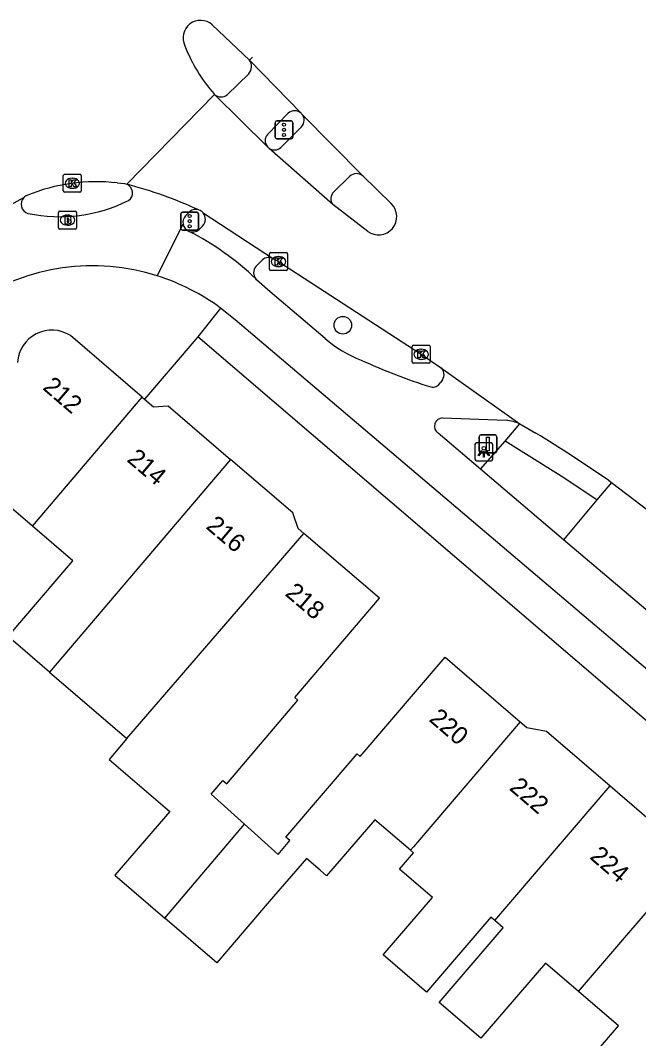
# Model space of a CAD drawing. Extents: x 162347 to 162868, y 381221 to 381813.
# Drawn here: x 162519 to 162553.4, y 381756.2 to 381812.9 of the extents above; entities that cross this region are included whole.
import ezdxf

# ---------------------------------------------------------------- set-up
doc = ezdxf.new("R2010")
doc.units = 0
for name, color, linetype in [('IMGEO_Berm_open', 7, 'Continuous'), ('IMGEO_Boom', 7, 'Continuous'), ('IMGEO_Brandkraan', 7, 'Continuous'), ('IMGEO_Fietspad_gesloten', 7, 'Continuous'), ('IMGEO_Kolk', 7, 'Continuous'), ('IMGEO_Lichtpunt', 7, 'Continuous'), ('IMGEO_Pand', 7, 'Continuous'), ('IMGEO_Pand_nummerreeks', 7, 'Continuous'), ('IMGEO_Rijbaan_lokaal_gesloten', 7, 'Continuous'), ('IMGEO_Rijbaan_regionaal_gesloten', 7, 'Continuous'), ('IMGEO_Verkeersbordpaal', 7, 'Continuous'), ('IMGEO_Verkeerseiland_groen', 7, 'Continuous'), ('IMGEO_Verkeersregelinstallatiepaal', 7, 'Continuous'), ('IMGEO_Voetpad_open', 7, 'Continuous')]:
    doc.layers.add(name, color=color, linetype=linetype)

msp = doc.modelspace()

# ---------------------------------------------------------------- linework, layer by layer
at = {"layer": 'IMGEO_Berm_open'}
msp.add_lwpolyline([(162551.096, 381786.201), (162549.242, 381783.987)], dxfattribs=at)
at = {"layer": 'IMGEO_Boom'}
msp.add_circle((162536.958, 381795.925), 0.489, dxfattribs=at)
at = {"layer": 'IMGEO_Brandkraan'}
for p, q in [((162521.217, 381802.273), (162522.069, 381802.273)), ((162521.142, 381801.347), (162521.142, 381802.199)), ((162521.63, 381802.053), (162521.655, 381802.053)), ((162522.143, 381802.199), (162522.143, 381801.347)), ((162522.069, 381801.273), (162521.217, 381801.273)), ((162521.653, 381801.493), (162521.628, 381801.493))]:
    msp.add_line(p, q, dxfattribs=at)
for points in [[(162521.217, 381802.273), (162522.069, 381802.273)], [(162521.142, 381801.347), (162521.142, 381802.199)], [(162521.49, 381801.973), (162521.49, 381801.573), (162521.703, 381801.573)], [(162521.721, 381801.973), (162521.49, 381801.973)], [(162521.669, 381801.892), (162521.615, 381801.892), (162521.615, 381801.816)], [(162521.615, 381801.816), (162521.668, 381801.816)], [(162521.677, 381801.74), (162521.615, 381801.74), (162521.615, 381801.659)], [(162521.615, 381801.659), (162521.677, 381801.659)], [(162522.143, 381802.199), (162522.143, 381801.347)], [(162522.069, 381801.273), (162521.217, 381801.273)]]:
    msp.add_lwpolyline(points, dxfattribs=at)
for centre, radius, start, end in [((162521.219, 381802.197), 0.0765, 91.552, 178.448), ((162521.219, 381802.197), 0.0765, 91.552, 178.448), ((162522.067, 381802.197), 0.0765, 1.552, 88.448), ((162522.067, 381802.197), 0.0765, 1.552, 88.448), ((162521.67, 381801.854), 0.0379, 267.8285, 90.9355), ((162521.678, 381801.699), 0.0404, 269.8759, 90.5077), ((162521.725, 381801.828), 0.145, 59.4692, 91.5367), ((162521.75, 381801.875), 0.0922, 285.5137, 58.1501), ((162521.755, 381801.683), 0.105, 301.3115, 78.989), ((162521.219, 381801.349), 0.0765, 181.552, 268.448), ((162521.219, 381801.349), 0.0765, 181.552, 268.448), ((162521.709, 381801.824), 0.251, 268.6676, 293.5347), ((162522.067, 381801.349), 0.0765, 271.552, 358.448), ((162522.067, 381801.349), 0.0765, 271.552, 358.448)]:
    msp.add_arc(centre, radius, start, end, dxfattribs=at)
for centre, major_axis, ratio, start_param, end_param in [((162521.629, 381801.773), (-0.387, 0.002), 0.722429, 4.712389, 7.853982), ((162521.654, 381801.773), (-0.39, 0.002), 0.717154, 1.570796, 4.712389)]:
    msp.add_ellipse(centre, major_axis=major_axis, ratio=ratio, start_param=start_param, end_param=end_param, dxfattribs=at)
at = {"layer": 'IMGEO_Fietspad_gesloten'}
for points in [[(162531.733, 381809.922), (162530.517, 381808.754)], [(162532.769, 381806.547), (162533.916, 381807.72)], [(162528.204, 381802.012), (162528.441, 381802.254)], [(162526.639, 381798.672), (162528.075, 381801.544)], [(162535.98, 381795.182), (162532.926, 381797.791), (162532.162, 381798.458), (162532.122, 381798.501)], [(162672.31, 381676.305), (162668.485, 381679.538), (162656.302, 381689.888), (162620.898, 381719.907), (162611.83, 381727.598), (162578.489, 381755.878), (162530.974, 381796.217), (162530.162, 381796.875)], [(162542.504, 381792.89), (162542.371, 381792.719)], [(162542.51, 381790.77), (162546.042, 381790.644)], [(162544.625, 381787.907), (162542.255, 381789.919)], [(162549.242, 381783.987), (162544.625, 381787.907)], [(162555.254, 381778.882), (162549.242, 381783.987)]]:
    msp.add_lwpolyline(points, dxfattribs=at)
for centre, radius, start, end in [((162531.289, 381810.311), 0.59, 318.7865, 37.0567), ((162530.176, 381809.157), 0.527, 227.4734, 310.2252), ((162534.277, 381807.332), 0.53, 47.2183, 132.9407), ((162533.161, 381806.201), 0.523, 138.5544, 220.7794), ((162524.744, 381803.291), 0.514, 304.8012, 67.8932), ((162519.591, 381802.656), 0.532, 134.2456, 253.9478), ((162521.199, 381810.556), 8.593, 258.2131, 296.5358), ((162528.773, 381801.823), 0.544, 71.1441, 127.6342), ((162528.606, 381801.649), 0.541, 137.9393, 191.2399), ((162528.601, 381801.651), 0.537, 191.524, 249.2472), ((162521.373, 381787.361), 15.48, 46.0225, 62.9577), ((162523.035, 381787.25), 11.977, 72.4855, 123.5061), ((162523.033, 381787.25), 11.978, 53.4724, 72.4775), ((162540.493, 381800.446), 6.934, 229.391, 248.7405), ((162552.493, 381825.872), 35.036, 245.5277, 252.316), ((162542.067, 381793.174), 0.521, 327.0291, 51.3842), ((162541.967, 381792.934), 0.457, 255.1251, 331.9605), ((162542.528, 381790.301), 0.47, 92.2296, 234.4089), ((162545.745, 381788.097), 2.564, 65.5334, 83.3489)]:
    msp.add_arc(centre, radius, start, end, dxfattribs=at)
at = {"layer": 'IMGEO_Kolk'}
for p, q in [((162521.409, 381803.397), (162521.409, 381804.249)), ((162521.484, 381804.323), (162522.336, 381804.323)), ((162521.897, 381804.103), (162521.922, 381804.103)), ((162522.41, 381804.249), (162522.41, 381803.397)), ((162521.92, 381803.543), (162521.895, 381803.543)), ((162522.336, 381803.323), (162521.484, 381803.323)), ((162532.954, 381799.968), (162533.806, 381799.968)), ((162532.879, 381799.042), (162532.879, 381799.894)), ((162533.367, 381799.748), (162533.392, 381799.748)), ((162533.88, 381799.894), (162533.88, 381799.042)), ((162533.806, 381798.968), (162532.954, 381798.968)), ((162533.39, 381799.188), (162533.365, 381799.188)), ((162540.816, 381793.881), (162540.816, 381794.733)), ((162540.891, 381794.807), (162541.743, 381794.807)), ((162541.304, 381794.587), (162541.329, 381794.587)), ((162541.817, 381794.733), (162541.817, 381793.881)), ((162541.743, 381793.807), (162540.891, 381793.807)), ((162541.327, 381794.027), (162541.302, 381794.027))]:
    msp.add_line(p, q, dxfattribs=at)
for points in [[(162521.409, 381803.397), (162521.409, 381804.249)], [(162521.484, 381804.323), (162522.336, 381804.323)], [(162521.73, 381804.023), (162521.853, 381804.023), (162521.853, 381803.872), (162521.983, 381804.023), (162522.147, 381804.023), (162522.001, 381803.872), (162522.154, 381803.623), (162522.002, 381803.623), (162521.917, 381803.787), (162521.853, 381803.72), (162521.853, 381803.623), (162521.73, 381803.623), (162521.73, 381804.023)], [(162522.41, 381804.249), (162522.41, 381803.397)], [(162522.336, 381803.323), (162521.484, 381803.323)], [(162532.954, 381799.968), (162533.806, 381799.968)], [(162532.879, 381799.042), (162532.879, 381799.894)], [(162533.2, 381799.668), (162533.323, 381799.668), (162533.323, 381799.517), (162533.453, 381799.668), (162533.617, 381799.668), (162533.471, 381799.517), (162533.624, 381799.268), (162533.472, 381799.268), (162533.387, 381799.432), (162533.323, 381799.365), (162533.323, 381799.268), (162533.2, 381799.268), (162533.2, 381799.668)], [(162533.88, 381799.894), (162533.88, 381799.042)], [(162533.806, 381798.968), (162532.954, 381798.968)], [(162540.816, 381793.881), (162540.816, 381794.733)], [(162540.891, 381794.807), (162541.743, 381794.807)], [(162541.137, 381794.507), (162541.26, 381794.507), (162541.26, 381794.356), (162541.39, 381794.507), (162541.554, 381794.507), (162541.408, 381794.356), (162541.561, 381794.107), (162541.409, 381794.107), (162541.324, 381794.271), (162541.26, 381794.204), (162541.26, 381794.107), (162541.137, 381794.107), (162541.137, 381794.507)], [(162541.817, 381794.733), (162541.817, 381793.881)], [(162541.743, 381793.807), (162540.891, 381793.807)]]:
    msp.add_lwpolyline(points, dxfattribs=at)
for centre, start, end in [((162521.486, 381804.247), 91.552, 178.448), ((162521.486, 381804.247), 91.552, 178.448), ((162522.334, 381804.247), 1.552, 88.448), ((162522.334, 381804.247), 1.552, 88.448), ((162521.486, 381803.399), 181.552, 268.448), ((162521.486, 381803.399), 181.552, 268.448), ((162522.334, 381803.399), 271.552, 358.448), ((162522.334, 381803.399), 271.552, 358.448), ((162532.956, 381799.892), 91.552, 178.448), ((162532.956, 381799.892), 91.552, 178.448), ((162533.804, 381799.892), 1.552, 88.448), ((162533.804, 381799.892), 1.552, 88.448), ((162532.956, 381799.044), 181.552, 268.448), ((162532.956, 381799.044), 181.552, 268.448), ((162533.804, 381799.044), 271.552, 358.448), ((162533.804, 381799.044), 271.552, 358.448), ((162540.893, 381794.731), 91.552, 178.448), ((162540.893, 381794.731), 91.552, 178.448), ((162541.741, 381794.731), 1.552, 88.448), ((162541.741, 381794.731), 1.552, 88.448), ((162540.893, 381793.883), 181.552, 268.448), ((162540.893, 381793.883), 181.552, 268.448), ((162541.741, 381793.883), 271.552, 358.448), ((162541.741, 381793.883), 271.552, 358.448)]:
    msp.add_arc(centre, 0.0765, start, end, dxfattribs=at)
for centre, major_axis, ratio, start_param, end_param in [((162521.896, 381803.823), (-0.387, 0.002), 0.722429, 4.712389, 7.853982), ((162521.921, 381803.823), (-0.39, 0.002), 0.717154, 1.570796, 4.712389), ((162533.366, 381799.468), (-0.387, 0.002), 0.722429, 4.712389, 7.853982), ((162533.391, 381799.468), (-0.39, 0.002), 0.717154, 1.570796, 4.712389), ((162541.303, 381794.307), (-0.387, 0.002), 0.722429, 4.712389, 7.853982), ((162541.328, 381794.307), (-0.39, 0.002), 0.717154, 1.570796, 4.712389)]:
    msp.add_ellipse(centre, major_axis=major_axis, ratio=ratio, start_param=start_param, end_param=end_param, dxfattribs=at)
at = {"layer": 'IMGEO_Lichtpunt'}
for p, q in [((162544.306, 381789.283), (162544.306, 381788.476)), ((162544.306, 381789.283), (162544.306, 381788.476)), ((162545.208, 381789.378), (162544.4, 381789.378)), ((162545.208, 381789.378), (162544.4, 381789.378)), ((162545.302, 381788.476), (162545.302, 381789.283)), ((162545.302, 381788.476), (162545.302, 381789.283)), ((162544.4, 381788.382), (162545.208, 381788.382)), ((162544.4, 381788.382), (162545.208, 381788.382))]:
    msp.add_line(p, q, dxfattribs=at)
for points in [[(162544.68, 381788.947), (162544.719, 381788.919), (162544.531, 381788.657), (162544.493, 381788.684), (162544.68, 381788.947)], [(162544.782, 381788.899), (162544.829, 381788.899), (162544.829, 381788.577), (162544.782, 381788.577), (162544.782, 381788.899)], [(162544.892, 381788.919), (162544.93, 381788.946), (162545.117, 381788.684), (162545.078, 381788.656), (162544.892, 381788.919)]]:
    msp.add_lwpolyline(points, dxfattribs=at)
msp.add_circle((162544.805, 381789.081), 0.0994, dxfattribs=at)
for centre, start, end in [((162544.4, 381789.283), 90, 180), ((162544.4, 381789.283), 90, 180), ((162545.208, 381789.283), 0, 90), ((162545.208, 381789.283), 0, 90), ((162544.4, 381788.476), 180, 270), ((162544.4, 381788.476), 180, 270), ((162545.208, 381788.476), 270, 0), ((162545.208, 381788.476), 270, 360)]:
    msp.add_arc(centre, 0.0946, start, end, dxfattribs=at)
at = {"layer": 'IMGEO_Pand'}
for points in [[(162525.8, 381791.919), (162521.807, 381795.349)], [(162519.691, 381784.738), (162525.8, 381791.919)], [(162525.8, 381791.919), (162525.921, 381791.816)], [(162525.921, 381791.816), (162526.43, 381791.378), (162527.242, 381791.44), (162530.708, 381788.463)], [(162530.708, 381788.463), (162520.639, 381776.627)], [(162534.792, 381784.344), (162534.48, 381784.612), (162534.173, 381785.486), (162530.708, 381788.463)], [(162519.691, 381784.738), (162517.175, 381786.899), (162514.963, 381784.324), (162511.88, 381786.972), (162511.997, 381787.108)], [(162520.639, 381776.627), (162518.332, 381778.608), (162521.939, 381782.807), (162519.691, 381784.738)], [(162524.95, 381772.924), (162534.792, 381784.344)], [(162531.492, 381768.158), (162529.63, 381769.834), (162530.283, 381770.594), (162530.5, 381770.409), (162534.458, 381775.063), (162534.29, 381775.205), (162538.993, 381780.735), (162534.792, 381784.344)], [(162531.492, 381768.158), (162533.357, 381766.479), (162534.018, 381767.249), (162533.788, 381767.446), (162537.755, 381772.079), (162537.922, 381771.935), (162542.644, 381777.449), (162546.834, 381773.85)], [(162520.639, 381776.627), (162524.95, 381772.924)], [(162546.834, 381773.85), (162540.889, 381766.907), (162540.722, 381766.711)], [(162546.834, 381773.85), (162547.196, 381773.539), (162548.292, 381773.333), (162551.834, 381770.291)], [(162524.95, 381772.924), (162523.954, 381771.765), (162525.906, 381770.088), (162527.328, 381768.866), (162524.282, 381765.32), (162527.053, 381762.94)], [(162545.414, 381762.795), (162551.834, 381770.291)], [(162551.834, 381770.291), (162555.99, 381766.721), (162556.045, 381765.985), (162556.129, 381765.913)], [(162540.722, 381766.711), (162538.745, 381768.41), (162536.06, 381765.284), (162535.696, 381765.596), (162534.93, 381766.255), (162532.866, 381763.852), (162529.947, 381760.454), (162527.053, 381762.94)], [(162527.053, 381762.94), (162531.492, 381768.158)], [(162545.414, 381762.795), (162545.193, 381762.985), (162541.614, 381758.819), (162539.208, 381760.885), (162541.951, 381764.078), (162540.117, 381765.654), (162540.897, 381766.561), (162540.722, 381766.711)], [(162550.073, 381758.842), (162556.129, 381765.913)], [(162550.073, 381758.842), (162548.228, 381760.427), (162544.641, 381756.25), (162542.324, 381758.24), (162545.887, 381762.388), (162545.414, 381762.795)], [(162548.456, 381744.573), (162545.715, 381746.927), (162548.354, 381750), (162548.831, 381750.555), (162548.102, 381751.181), (162550.149, 381753.565), (162549.716, 381753.937), (162552.292, 381756.936), (162550.073, 381758.842)]]:
    msp.add_lwpolyline(points, dxfattribs=at)
msp.add_arc((162520.772, 381793.741), 1.913, 57.2245, 176.6348, dxfattribs=at)
at = {"layer": 'IMGEO_Rijbaan_lokaal_gesloten'}
for points in [[(162531.76, 381810.666), (162534.637, 381807.721)], [(162532.765, 381805.859), (162529.82, 381808.768)], [(162534.637, 381807.721), (162534.665, 381807.693)], [(162534.665, 381807.693), (162538.071, 381804.24)], [(162532.868, 381805.767), (162532.765, 381805.859)], [(162536.404, 381802.641), (162532.868, 381805.767)], [(162538.071, 381804.24), (162539.651, 381802.697)], [(162538.343, 381801.148), (162536.404, 381802.641)], [(162529.183, 381802.18), (162533.097, 381799.629)], [(162533.097, 381799.629), (162533.177, 381799.58), (162533.38, 381799.468), (162541.317, 381794.307), (162542.345, 381793.615), (162542.392, 381793.581)], [(162542.392, 381793.581), (162546.807, 381790.431)], [(162546.807, 381790.431), (162547.695, 381789.925)], [(162551.732, 381787.297), (162551.904, 381787.167)], [(162551.904, 381787.167), (162554.472, 381785.229), (162555.268, 381784.639)]]:
    msp.add_lwpolyline(points, dxfattribs=at)
for centre, radius, start, end in [((162518.855, 381780.367), 24.179, 65.3259, 75.4298), ((162528.771, 381801.822), 0.545, 40.9709, 70.9736), ((162538.94, 381801.971), 1.016, 234.0391, 45.6043), ((162502.063, 381715.412), 87.376, 55.35718, 58.5163)]:
    msp.add_arc(centre, radius, start, end, dxfattribs=at)
at = {"layer": 'IMGEO_Rijbaan_regionaal_gesloten'}
for points in [[(162529.697, 381812.64), (162531.76, 381810.666)], [(162531.941, 381810.835), (162531.76, 381810.666)], [(162529.82, 381808.768), (162524.938, 381803.768)], [(162529.82, 381808.768), (162529.793, 381808.795)], [(162524.407, 381803.842), (162524.804, 381803.803), (162524.938, 381803.768)], [(162514.507, 381800.448), (162519.22, 381803.037)]]:
    msp.add_lwpolyline(points, dxfattribs=at)
for centre, radius, start, end in [((162529.045, 381811.912), 0.978, 48.1333, 206.8112), ((162536.889, 381814.922), 9.375, 201.6005, 220.8107), ((162523.235, 381793.838), 10.072, 83.3155, 112.4814), ((162519.597, 381802.646), 0.543, 113.1551, 133.8999)]:
    msp.add_arc(centre, radius, start, end, dxfattribs=at)
at = {"layer": 'IMGEO_Verkeersbordpaal'}
for p, q in [((162544.638, 381789.818), (162545.428, 381789.818)), ((162545.428, 381789.818), (162544.638, 381789.818)), ((162544.538, 381788.918), (162544.538, 381789.718)), ((162544.538, 381789.718), (162544.538, 381788.918)), ((162545.528, 381789.718), (162545.528, 381788.918)), ((162545.528, 381788.918), (162545.528, 381789.718)), ((162545.428, 381788.818), (162544.638, 381788.818)), ((162544.638, 381788.818), (162545.428, 381788.818))]:
    msp.add_line(p, q, dxfattribs=at)
msp.add_lwpolyline([(162544.958, 381789.693), (162545.108, 381789.693), (162545.108, 381788.943), (162544.958, 381788.943), (162544.958, 381789.693)], dxfattribs=at)
for centre, start, end in [((162544.638, 381789.718), 90, 180), ((162544.638, 381789.718), 90, 180), ((162545.428, 381789.718), 0, 90), ((162545.428, 381789.718), 360, 90), ((162544.638, 381788.918), 180, 270), ((162544.638, 381788.918), 180, 270), ((162545.428, 381788.918), 270, 0), ((162545.428, 381788.918), 270, 0)]:
    msp.add_arc(centre, 0.1, start, end, dxfattribs=at)
at = {"layer": 'IMGEO_Verkeerseiland_groen'}
msp.add_lwpolyline([(162544.625, 381787.907), (162545.983, 381789.478)], dxfattribs=at)
at = {"layer": 'IMGEO_Verkeersregelinstallatiepaal'}
for p, q in [((162533.19, 381806.397), (162533.19, 381807.197)), ((162533.19, 381807.197), (162533.19, 381806.397)), ((162533.29, 381807.297), (162534.08, 381807.297)), ((162534.08, 381807.297), (162533.29, 381807.297)), ((162534.18, 381807.197), (162534.18, 381806.397)), ((162534.18, 381806.397), (162534.18, 381807.197)), ((162534.08, 381806.297), (162533.29, 381806.297)), ((162533.29, 381806.297), (162534.08, 381806.297)), ((162527.94, 381801.316), (162527.94, 381802.116)), ((162527.94, 381802.116), (162527.94, 381801.316)), ((162528.04, 381802.216), (162528.83, 381802.216)), ((162528.83, 381802.216), (162528.04, 381802.216)), ((162528.93, 381802.116), (162528.93, 381801.316)), ((162528.93, 381801.316), (162528.93, 381802.116)), ((162528.83, 381801.216), (162528.04, 381801.216)), ((162528.04, 381801.216), (162528.83, 381801.216))]:
    msp.add_line(p, q, dxfattribs=at)
for centre in [(162533.685, 381807.087), (162533.685, 381806.797), (162533.685, 381806.507), (162528.435, 381802.006), (162528.435, 381801.716), (162528.435, 381801.426)]:
    msp.add_circle(centre, 0.085, dxfattribs=at)
for centre, start, end in [((162533.29, 381807.197), 90, 180), ((162533.29, 381807.197), 90, 180), ((162534.08, 381807.197), 0, 90), ((162534.08, 381807.197), 360, 90), ((162533.29, 381806.397), 180, 270), ((162533.29, 381806.397), 180, 270), ((162534.08, 381806.397), 270, 0), ((162534.08, 381806.397), 270, 0), ((162528.04, 381802.116), 90, 180), ((162528.04, 381802.116), 90, 180), ((162528.83, 381802.116), 0, 90), ((162528.83, 381802.116), 360, 90), ((162528.04, 381801.316), 180, 270), ((162528.04, 381801.316), 180, 270), ((162528.83, 381801.316), 270, 0), ((162528.83, 381801.316), 270, 0)]:
    msp.add_arc(centre, 0.1, start, end, dxfattribs=at)
at = {"layer": 'IMGEO_Voetpad_open'}
for points in [[(162533.515, 381805.813), (162534.661, 381806.965)], [(162537.344, 381804.213), (162536.456, 381803.339)], [(162529.158, 381801.441), (162528.95, 381801.243)], [(162532.488, 381799.57), (162532.121, 381799.195)], [(162530.162, 381796.875), (162528.884, 381795.273)], [(162528.884, 381795.273), (162525.921, 381791.816)], [(162607.811, 381727.718), (162581.778, 381750), (162528.884, 381795.273)], [(162545.983, 381789.478), (162546.807, 381790.431)], [(162551.096, 381786.201), (162550.108, 381786.864), (162549.257, 381787.43), (162545.983, 381789.478)], [(162551.904, 381787.167), (162551.096, 381786.201)]]:
    msp.add_lwpolyline(points, dxfattribs=at)
for centre, radius, start, end in [((162534.279, 381807.331), 0.529, 316.245, 43.1254), ((162533.162, 381806.201), 0.525, 235.884, 312.2495), ((162537.723, 381803.804), 0.558, 51.4112, 132.8426), ((162536.797, 381802.963), 0.508, 132.1805, 219.2983), ((162528.774, 381801.824), 0.542, 315.0796, 41.0453), ((162528.601, 381801.65), 0.536, 249.2118, 310.5737), ((162532.839, 381799.122), 0.569, 62.9863, 128.0808), ((162532.535, 381798.849), 0.54, 140.0916, 220.0736)]:
    msp.add_arc(centre, radius, start, end, dxfattribs=at)

# ---------------------------------------------------------------- texts
at = {"layer": 'IMGEO_Pand_nummerreeks'}
for s, rotation, p in [('212', 319.3385, (162520.211, 381792.396)), ('214', 319.7109, (162524.896, 381788.386)), ('216', 319.7096, (162529.293, 381784.658)), ('218', 319.7096, (162533.695, 381780.927)), ('220', 319.4231, (162541.702, 381773.939)), ('222', 319.4231, (162546.169, 381770.113)), ('224', 319.4259, (162550.643, 381766.281))]:
    msp.add_text(s, height=1, rotation=rotation, dxfattribs=at).set_placement(p)

doc.saveas('drawing.dxf')
